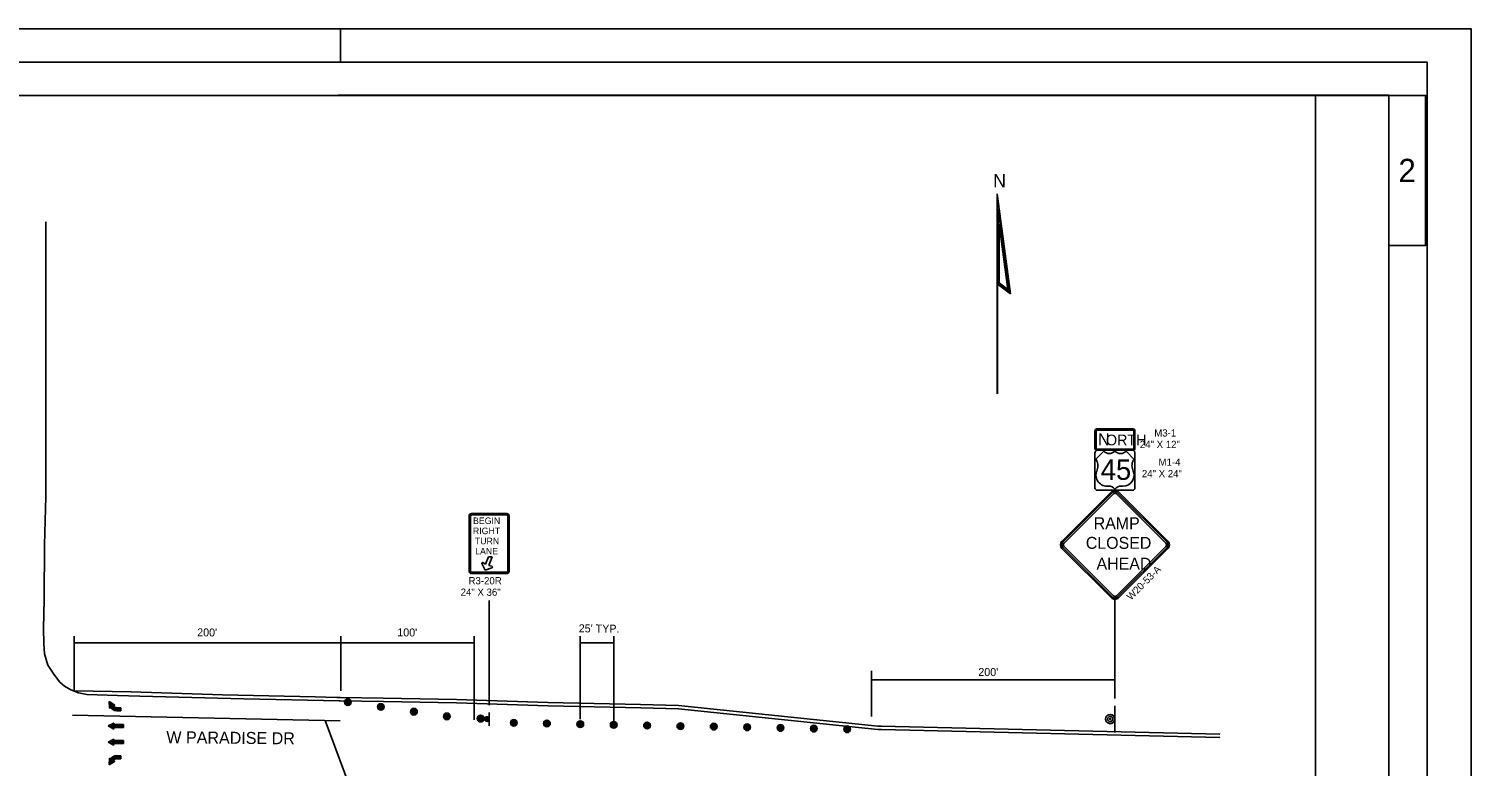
# Model space of a CAD drawing. Extents: x 360065 to 362124, y 174333 to 175433.
# Drawn here: x 361043 to 362124, y 174880 to 175433 of the extents above; entities that cross this region are included whole.
import ezdxf

# ---------------------------------------------------------------- set-up
doc = ezdxf.new("R2010")
doc.units = 0
for name, color, linetype in [('Default', 7, 'Continuous'), ('P_ALI_100_Equation', 7, 'Continuous'), ('P_ALI_100_PIData', 7, 'Continuous'), ('P_ALI_100_Sta', 7, 'Continuous'), ('P_ALI_20', 7, 'Continuous'), ('P_ALI_200_Equation', 7, 'Continuous'), ('P_ALI_20_Equation', 7, 'Continuous'), ('P_ALI_20_Sta', 7, 'Continuous'), ('P_ALI_500_Equation', 7, 'Continuous'), ('P_ALI_500_PIData', 7, 'Continuous'), ('P_ALI_500_Sta', 7, 'Continuous'), ('P_ALI_50_Equation', 7, 'Continuous'), ('P_ALI_50_Tic', 7, 'Continuous')]:
    doc.layers.add(name, color=color, linetype=linetype)

msp = doc.modelspace()

# ---------------------------------------------------------------- linework, layer by layer
for p, q in [((361251.6, 175433), (361301.6, 175433)), ((361276.6, 175433), (361276.6, 175408)), ((362074.1, 175433), (362124.1, 175433)), ((362124.1, 175383), (362124.1, 175433)), ((360487.4, 175383), (362062.4, 175383)), ((362062.4, 174383), (362062.4, 175383))]:
    msp.add_line(p, q)
msp.add_lwpolyline([(362062.4, 175383), (362089.9, 175383), (362089.9, 175270.5), (362062.4, 175270.5)], close=True)
at = {"layer": 'Default'}
msp.add_lwpolyline([(362007.4, 175383), (362007.4, 174984.3), (362007.4, 174408.5), (360514, 174408), (360560.9, 175383)], close=True, dxfattribs=at)
msp.add_lwpolyline([(362007.4, 175383), (362007.4, 174984.3), (362007.4, 174408.5), (360514, 174408), (360560.9, 175383)], close=True, dxfattribs=at)
msp.add_lwpolyline([(362007.4, 175383), (362007.4, 174984.3), (362007.4, 174408.5), (360514, 174408), (360560.9, 175383)], close=True, dxfattribs=at)
at = {"layer": 'P_ALI_100_Equation'}
for p, q in [((361778.8, 175234.2), (361768.8, 175309.2)), ((361768.8, 175241.7), (361768.8, 175309.2)), ((361769.6, 175242), (361769.6, 175297.9)), ((361777.9, 175235.8), (361769.6, 175297.9)), ((361770.3, 175242.4), (361770.3, 175286.6)), ((361776.9, 175237.5), (361770.3, 175286.6)), ((361768.8, 175241.7), (361778.8, 175234.2)), ((361768.8, 175159.2), (361768.8, 175241.7)), ((361769.1, 175159.2), (361769.1, 175241.5)), ((361769.6, 175242), (361777.9, 175235.8)), ((361770.3, 175242.4), (361776.9, 175237.5))]:
    msp.add_line(p, q, dxfattribs=at)
msp.add_lwpolyline([(361768.9, 175309.1), (361768.8, 175309.1)], dxfattribs=at)
at = {"layer": 'P_ALI_100_PIData'}
for p, q in [((361388, 174925.8), (361388, 175004.3)), ((361857.1, 174931), (361857.1, 175005.2)), ((361076.9, 174936.6), (361076.9, 174977.6)), ((361076.9, 174972.6), (361276.9, 174972.6)), ((361276.9, 174936.6), (361276.9, 174977.6)), ((361276.9, 174972.6), (361376.9, 174972.6)), ((361376.9, 174915), (361376.9, 174977.6)), ((361456.4, 174915.5), (361456.4, 174977.6)), ((361456.4, 174972.6), (361481.4, 174972.6)), ((361481.4, 174914), (361481.4, 174977.6)), ((361674.6, 174917.4), (361674.6, 174951.6)), ((361674.6, 174944.9), (361857.1, 174944.9)), ((361265.1, 174914.4), (361305.2, 174806.8))]:
    msp.add_line(p, q, dxfattribs=at)
at = {"layer": 'P_ALI_100_Sta'}
for p, q in [((361304.6, 174929.6), (361304.6, 174929.6)), ((361329.4, 174926.1), (361329.4, 174926.1)), ((361354.1, 174922.5), (361354.1, 174922.5)), ((361378.9, 174919), (361378.9, 174919)), ((361388, 174920.5), (361388, 174910.5)), ((361857.1, 174925.5), (361857.1, 174905.5)), ((361404.2, 174915.3), (361404.2, 174915.3)), ((361428.9, 174912.2), (361428.9, 174912.2)), ((361453.9, 174911.8), (361453.9, 174911.8)), ((361478.9, 174911.3), (361478.9, 174911.3)), ((361503.9, 174910.8), (361503.9, 174910.8)), ((361528.9, 174910.3), (361528.9, 174910.3)), ((361553.9, 174909.8), (361553.9, 174909.8)), ((361578.9, 174909.3), (361578.9, 174909.3)), ((361603.9, 174908.8), (361603.9, 174908.8)), ((361628.9, 174908.3), (361628.9, 174908.3)), ((361653.9, 174907.8), (361653.9, 174907.8)), ((361678.9, 174907.4), (361678.9, 174907.4))]:
    msp.add_line(p, q, dxfattribs=at)
for centre, radius in [((361282.2, 174928.1), 2.5), ((361282.2, 174928.1), 2), ((361282.2, 174928.1), 1.5), ((361282.2, 174928.1), 1), ((361282.2, 174928.1), 0.5), ((361282.2, 174928.1), 0.25), ((361306.9, 174924.6), 2.5), ((361306.9, 174924.6), 2), ((361306.9, 174924.6), 1.5), ((361306.9, 174924.6), 1), ((361306.9, 174924.6), 0.5), ((361306.9, 174924.6), 0.25), ((361331.7, 174921), 2.5), ((361331.7, 174921), 2), ((361331.7, 174921), 1.5), ((361331.7, 174921), 1), ((361331.7, 174921), 0.5), ((361331.7, 174921), 0.25), ((361356.4, 174917.5), 2.5), ((361356.4, 174917.5), 2), ((361356.4, 174917.5), 1.5), ((361356.4, 174917.5), 1), ((361356.4, 174917.5), 0.5), ((361356.4, 174917.5), 0.25), ((361381.7, 174915.8), 2.5), ((361381.7, 174915.8), 2), ((361381.7, 174915.8), 1.5), ((361381.7, 174915.8), 1), ((361381.7, 174915.8), 0.5), ((361381.7, 174915.8), 0.25), ((361386.3, 174915.5), 1.75), ((361386.3, 174915.5), 1), ((361386.3, 174915.5), 0.25), ((361853.6, 174915.5), 3.5), ((361853.6, 174915.5), 2), ((361853.6, 174915.5), 0.5), ((361406.5, 174912.7), 2.5), ((361406.5, 174912.7), 2), ((361406.5, 174912.7), 1.5), ((361406.5, 174912.7), 1), ((361406.5, 174912.7), 0.5), ((361406.5, 174912.7), 0.25), ((361431.4, 174912.2), 2.5), ((361431.4, 174912.2), 2), ((361431.4, 174912.2), 1.5), ((361431.4, 174912.2), 1), ((361431.4, 174912.2), 0.5), ((361431.4, 174912.2), 0.25), ((361456.4, 174911.7), 2.5), ((361456.4, 174911.7), 2), ((361456.4, 174911.7), 1.5), ((361456.4, 174911.7), 1), ((361456.4, 174911.7), 0.5), ((361456.4, 174911.7), 0.25), ((361481.4, 174911.2), 2.5), ((361481.4, 174911.2), 2), ((361481.4, 174911.2), 1.5), ((361481.4, 174911.2), 1), ((361481.4, 174911.2), 0.5), ((361481.4, 174911.2), 0.25), ((361506.4, 174910.7), 2.5), ((361506.4, 174910.7), 2), ((361506.4, 174910.7), 1.5), ((361506.4, 174910.7), 1), ((361506.4, 174910.7), 0.5), ((361506.4, 174910.7), 0.25), ((361531.4, 174910.2), 2.5), ((361531.4, 174910.2), 2), ((361531.4, 174910.2), 1.5), ((361531.4, 174910.2), 1), ((361531.4, 174910.2), 0.5), ((361531.4, 174910.2), 0.25), ((361556.4, 174909.8), 2.5), ((361556.4, 174909.8), 2), ((361556.4, 174909.8), 1.5), ((361556.4, 174909.8), 1), ((361556.4, 174909.8), 0.5), ((361556.4, 174909.8), 0.25), ((361581.4, 174909.3), 2.5), ((361581.4, 174909.3), 2), ((361581.4, 174909.3), 1.5), ((361581.4, 174909.3), 1), ((361581.4, 174909.3), 0.5), ((361581.4, 174909.3), 0.25), ((361606.4, 174908.8), 2.5), ((361606.4, 174908.8), 2), ((361606.4, 174908.8), 1.5), ((361606.4, 174908.8), 1), ((361606.4, 174908.8), 0.5), ((361606.4, 174908.8), 0.25), ((361631.4, 174908.3), 2.5), ((361631.4, 174908.3), 2), ((361631.4, 174908.3), 1.5), ((361631.4, 174908.3), 1), ((361631.4, 174908.3), 0.5), ((361631.4, 174908.3), 0.25), ((361656.4, 174907.8), 2.5), ((361656.4, 174907.8), 2), ((361656.4, 174907.8), 1.5), ((361656.4, 174907.8), 1), ((361656.4, 174907.8), 0.5), ((361656.4, 174907.8), 0.25)]:
    msp.add_circle(centre, radius, dxfattribs=at)
at = {"layer": 'P_ALI_20'}
for points in [[(360424.1, 174333), (362124.1, 174333), (362124.1, 175433), (360424.1, 175433)], [(360436.1, 174358), (362091.1, 174358), (362091.1, 175408), (360436.1, 175408)]]:
    msp.add_lwpolyline(points, close=True, dxfattribs=at)
at = {"layer": 'P_ALI_200_Equation'}
msp.add_lwpolyline([(360424.1, 175433), (362124.1, 175433), (362124.1, 174333), (360424.1, 174333), (360424.1, 175433)], dxfattribs=at)
at = {"layer": 'P_ALI_20_Equation'}
msp.add_line((361055.7, 175082.2), (361055.7, 175288.2), dxfattribs=at)
for points in [[(361275.8, 174929.2), (361204.1, 174930.7), (361126.3, 174932.7), (361109.6, 174933.2), (361086.5, 174934), (361080.3, 174935.2), (361074.6, 174937.5), (361069.8, 174940.2), (361066.4, 174943.2), (361062.4, 174948.3), (361057.3, 174955.8), (361054.8, 174964.4), (361054.2, 174972.2), (361054, 174983), (361054.6, 175005.3), (361054.9, 175046.1), (361055.7, 175082.2)], [(361273.8, 174931.7), (361257.6, 174932.2), (361188.2, 174933.7), (361119.7, 174935.9), (361076.9, 174936.6), (361076.9, 174936.6), (361076.9, 174936.6)], [(361530.1, 174925.7), (361501.6, 174926.5), (361432.1, 174928), (361363.7, 174930.2), (361308.7, 174931.1), (361276.4, 174931.6), (361273.8, 174931.7)], [(361530.1, 174923.2), (361501.7, 174924), (361432.2, 174925.5), (361363.7, 174927.7), (361308.8, 174928.6), (361276.4, 174929.1), (361275.7, 174929.2)], [(361679.4, 174910.2), (361530.1, 174925.7)], [(361679.4, 174907.7), (361530.1, 174923.2)], [(361935.8, 174904.2), (361935.8, 174904.2), (361935.8, 174904.2), (361935.8, 174904.2), (361935.8, 174904.2), (361682, 174910.2), (361679.4, 174910.2)], [(361935.7, 174901.7), (361935.7, 174901.7), (361935.7, 174901.7), (361935.7, 174901.7), (361935.7, 174901.7), (361682.1, 174907.7), (361679.4, 174907.7)]]:
    msp.add_lwpolyline(points, dxfattribs=at)
at = {"layer": 'P_ALI_20_Sta'}
msp.add_lwpolyline([(360424.1, 175433), (362124.1, 175433), (362124.1, 174333), (360424.1, 174333)], close=True, dxfattribs=at)
at = {"layer": 'P_ALI_500_Equation'}
msp.add_line((361276.4, 174914.2), (361075.8, 174918.3), dxfattribs=at)
at = {"layer": 'P_ALI_500_PIData'}
for p, q in [((361107.5, 174925.9), (361103.3, 174928.6)), ((361103.3, 174928.6), (361103.6, 174923.6)), ((361105.3, 174924.6), (361103.4, 174928.1)), ((361104.9, 174924.4), (361103.4, 174927.1)), ((361105.7, 174924.9), (361103.7, 174928.3)), ((361106.1, 174925.1), (361104.6, 174927.8)), ((361106.5, 174925.3), (361105.4, 174927.2)), ((361106.9, 174925.5), (361106.2, 174926.7)), ((361104.6, 174924.2), (361103.5, 174926.1)), ((361104.2, 174924), (361103.5, 174925.1)), ((361103.6, 174923.6), (361104.6, 174924.2)), ((361103.8, 174923.7), (361103.6, 174924.1)), ((361106.5, 174925.3), (361107.5, 174925.9)), ((361107.3, 174925.8), (361107.1, 174926.2)), ((361112, 174923.9), (361108.9, 174923.9)), ((361112, 174923.5), (361108.9, 174923.5)), ((361112, 174923), (361108.9, 174923)), ((361112, 174922.6), (361108.9, 174922.6)), ((361112, 174922.1), (361108.9, 174922.1)), ((361112, 174921.7), (361108.9, 174921.7)), ((361112, 174921.7), (361112, 174923.9)), ((361112, 174922.8), (361112, 174922.8)), ((361102.4, 174910.3), (361106.8, 174912.5)), ((361102.4, 174910.3), (361106.8, 174908)), ((361113.9, 174910.5), (361102.8, 174910.5)), ((361113.9, 174910), (361102.9, 174910)), ((361113.9, 174910.9), (361103.7, 174910.9)), ((361113.9, 174909.6), (361103.8, 174909.6)), ((361106.8, 174911.4), (361104.6, 174911.4)), ((361106.8, 174909.1), (361104.7, 174909.1)), ((361106.8, 174911.8), (361105.5, 174911.8)), ((361106.8, 174908.7), (361105.5, 174908.7)), ((361106.8, 174912.3), (361106.4, 174912.3)), ((361106.8, 174908.2), (361106.4, 174908.2)), ((361106.8, 174912.5), (361106.8, 174908)), ((361113.9, 174911.4), (361106.8, 174911.4)), ((361113.9, 174909.1), (361106.8, 174909.1)), ((361113.9, 174911.4), (361113.9, 174909.1)), ((361113.9, 174910.3), (361113.9, 174910.3)), ((361102.4, 174898.2), (361106.8, 174900.5)), ((361102.4, 174898.2), (361106.8, 174896)), ((361113.9, 174898.4), (361102.8, 174898.4)), ((361113.9, 174898), (361102.9, 174898)), ((361113.9, 174898.9), (361103.7, 174898.9)), ((361113.9, 174897.5), (361103.8, 174897.5)), ((361106.8, 174899.3), (361104.6, 174899.3)), ((361106.8, 174897.1), (361104.7, 174897.1)), ((361106.8, 174899.8), (361105.5, 174899.8)), ((361106.8, 174896.6), (361105.5, 174896.6)), ((361106.8, 174900.2), (361106.4, 174900.2)), ((361106.8, 174896.2), (361106.4, 174896.2)), ((361106.8, 174900.5), (361106.8, 174896)), ((361113.9, 174899.3), (361106.8, 174899.3)), ((361113.9, 174897.1), (361106.8, 174897.1)), ((361113.9, 174899.3), (361113.9, 174897.1)), ((361113.9, 174898.2), (361113.9, 174898.2)), ((361103.3, 174881.1), (361103.6, 174886.1)), ((361107.5, 174883.8), (361103.3, 174881.1)), ((361104.9, 174885.3), (361103.4, 174882.6)), ((361105.3, 174885), (361103.4, 174881.6)), ((361104.2, 174885.7), (361103.5, 174884.6)), ((361104.6, 174885.5), (361103.5, 174883.6)), ((361103.6, 174886.1), (361104.6, 174885.5)), ((361103.8, 174885.9), (361103.6, 174885.6)), ((361105.7, 174884.8), (361103.7, 174881.4)), ((361106.1, 174884.6), (361104.6, 174881.9)), ((361106.5, 174884.4), (361105.4, 174882.5)), ((361106.9, 174884.1), (361106.2, 174883)), ((361106.5, 174884.4), (361107.5, 174883.8)), ((361107.3, 174883.9), (361107.1, 174883.5)), ((361112, 174888), (361108.9, 174888)), ((361112, 174887.5), (361108.9, 174887.5)), ((361112, 174887.1), (361108.9, 174887.1)), ((361112, 174886.6), (361108.9, 174886.6)), ((361112, 174886.2), (361108.9, 174886.2)), ((361112, 174885.7), (361108.9, 174885.7)), ((361112, 174888), (361112, 174885.7)), ((361112, 174886.9), (361112, 174886.9))]:
    msp.add_line(p, q, dxfattribs=at)
for centre, radius, start, end in [((361108.9, 174926.7), 5.03, 209.9967, 270), ((361108.9, 174926.7), 4.58, 209.9967, 270), ((361108.9, 174926.7), 4.13, 209.9967, 270), ((361108.9, 174926.7), 3.68, 209.9967, 270), ((361108.9, 174926.7), 3.23, 209.9967, 270), ((361108.9, 174926.7), 2.78, 209.9967, 270), ((361108.9, 174883), 5.03, 90, 150.0033), ((361108.9, 174883), 4.58, 90, 150.0033), ((361108.9, 174883), 4.13, 90, 150.0033), ((361108.9, 174883), 3.68, 90, 150.0033), ((361108.9, 174883), 3.23, 90, 150.0033), ((361108.9, 174883), 2.78, 90, 150.0033)]:
    msp.add_arc(centre, radius, start, end, dxfattribs=at)
at = {"layer": 'P_ALI_500_Sta'}
for p, q in [((361843.6, 175133), (361870.6, 175133)), ((361843.6, 175132.6), (361870.6, 175132.6)), ((361843.6, 175132.1), (361870.6, 175132.1)), ((361842.1, 175131.5), (361842.1, 175118.5)), ((361842.5, 175131.5), (361842.5, 175118.5)), ((361843, 175131.5), (361843, 175118.5)), ((361871.2, 175131.5), (361871.2, 175118.5)), ((361871.7, 175131.5), (361871.7, 175118.5)), ((361872.1, 175131.5), (361872.1, 175118.5)), ((361842.1, 175088.8), (361842.1, 175115.1)), ((361848.8, 175116.3), (361842.8, 175110.3)), ((361870.6, 175117.8), (361843.6, 175117.8)), ((361870.6, 175117.3), (361843.6, 175117.3)), ((361870.6, 175117), (361843.6, 175117)), ((361844, 175117), (361870.2, 175117)), ((361871.4, 175110.3), (361865.5, 175116.3)), ((361872.1, 175115.1), (361872.1, 175088.8)), ((361851.2, 175090.1), (361852.4, 175090.1)), ((361861.9, 175090.1), (361863.1, 175090.1)), ((361857.1, 175087), (361844, 175087)), ((361870.2, 175087), (361857.1, 175087)), ((361870.2, 175087), (361870.2, 175087)), ((361385.4, 175031.5), (361387.7, 175037.1)), ((361390.4, 175037.1), (361387.7, 175037.1)), ((361387.8, 175030.6), (361390.4, 175037.1)), ((361382.6, 175032), (361385, 175027.1)), ((361383.5, 175032.7), (361385.4, 175031.5)), ((361390.1, 175028.9), (361385, 175027.1)), ((361390, 175030.1), (361387.8, 175030.6))]:
    msp.add_line(p, q, dxfattribs=at)
for points in [[(361854.5, 175085.9), (361817.3, 175048.7)], [(361855.1, 175085.2), (361818, 175048.1)], [(361856, 175084.4), (361818.9, 175047.2)], [(361895.4, 175047.2), (361858.3, 175084.4)], [(361896.2, 175048.1), (361859.1, 175085.2)], [(361896.9, 175048.7), (361859.8, 175085.9)], [(361373, 175067.7), (361373, 175026.4)], [(361373.5, 175067.7), (361373.5, 175026.4)], [(361374.1, 175067.7), (361374.1, 175026.4)], [(361401.2, 175069.6), (361374.9, 175069.6)], [(361401.2, 175069.1), (361374.9, 175069.1)], [(361401.2, 175068.5), (361374.9, 175068.5)], [(361402, 175026.4), (361402, 175067.7)], [(361402.6, 175026.4), (361402.6, 175067.7)], [(361403, 175026.4), (361403, 175067.7)], [(361817.3, 175043.4), (361854.5, 175006.3)], [(361818, 175044.1), (361855.1, 175007)], [(361818.9, 175045), (361856, 175007.8)], [(361858.3, 175007.9), (361895.4, 175045)], [(361859.1, 175007), (361896.2, 175044.1)], [(361859.8, 175006.4), (361896.9, 175043.5)], [(361374.9, 175025.7), (361401.2, 175025.7)], [(361374.9, 175025), (361401.2, 175025)], [(361374.9, 175024.6), (361401.2, 175024.6)]]:
    msp.add_lwpolyline(points, dxfattribs=at)
for centre, radius, start, end in [((361843.6, 175131.5), 1.5, 90.7657, 180), ((361843.6, 175131.5), 1.12, 90, 180), ((361843.6, 175131.5), 0.625, 90, 180), ((361870.6, 175131.5), 1.5, 0, 90), ((361870.6, 175131.5), 1.12, 0, 90), ((361870.6, 175131.5), 0.625, 0, 90), ((361843.6, 175118.5), 1.5, 180, 270), ((361844, 175115.1), 1.87, 90, 180), ((361843.6, 175118.5), 1.12, 180, 270), ((361836.1, 175105.4), 8.33, 338.8697, 35.952), ((361843.6, 175118.5), 0.625, 180, 270), ((361852.9, 175120.5), 5.95, 225.5728, 314.4272), ((361861.3, 175120.5), 5.95, 225.5728, 314.4272), ((361878.2, 175105.5), 8.33, 144.2681, 203.1411), ((361870.2, 175115.1), 1.87, 0, 90), ((361870.6, 175118.5), 1.12, 270, 360), ((361870.6, 175118.5), 0.625, 270, 360), ((361870.6, 175118.5), 1.5, 270, 360), ((361851.2, 175098.4), 8.33, 151.2519, 270.0001), ((361863.1, 175098.4), 8.33, 269.9999, 26.8465), ((361844, 175088.8), 1.87, 180, 270), ((361852.3, 175084.1), 6.03, 37.2122, 89.6577), ((361861.9, 175084.1), 6.03, 90.3423, 142.7878), ((361870.2, 175088.8), 1.87, 270, 360), ((361857.1, 175083.2), 3.75, 44.9981, 135), ((361857.1, 175083.2), 2.8, 44.9981, 135), ((361857.1, 175083.2), 1.61, 44.9981, 135), ((361374.9, 175067.7), 1.88, 90, 180), ((361374.9, 175067.7), 1.41, 90, 180), ((361374.9, 175067.7), 0.781, 90, 180), ((361401.2, 175067.7), 1.88, 0, 90), ((361401.2, 175067.7), 1.41, 0, 90), ((361401.2, 175067.7), 0.781, 0, 90), ((361820, 175046.1), 3.75, 135, 225), ((361820, 175046.1), 2.8, 135, 225), ((361820, 175046.1), 1.61, 135, 225), ((361894.2, 175046.1), 1.61, 315, 45), ((361894.2, 175046.1), 2.8, 315, 45), ((361894.2, 175046.1), 3.75, 315, 45), ((361374.9, 175026.4), 1.88, 180, 270), ((361374.9, 175026.4), 1.41, 180, 270), ((361374.9, 175026.4), 0.781, 180, 270), ((361383.2, 175032.2), 0.625, 57.4706, 200.3737), ((361389.9, 175029.5), 0.625, 292.3864, 78.7997), ((361401.2, 175026.4), 1.41, 270, 0), ((361401.2, 175026.4), 1.88, 270, 0), ((361401.2, 175026.4), 0.781, 270, 0), ((361857.1, 175009), 3.75, 225.0072, 315.6509), ((361857.1, 175009), 2.8, 225.0072, 315.6509), ((361857.1, 175009), 1.61, 225.0072, 315.6509)]:
    msp.add_arc(centre, radius, start, end, dxfattribs=at)
at = {"layer": 'P_ALI_50_Tic'}
msp.add_lwpolyline([(362062, 175383.5), (360487.4, 175383), (360487.7, 174408)], dxfattribs=at)

# ---------------------------------------------------------------- texts
msp.add_text('2', height=17.5, rotation=360).set_placement((362069.6, 175318))
at = {"layer": 'P_ALI_100_Equation'}
msp.add_text('N', height=10, dxfattribs=at).set_placement((361765.8, 175314.1))
at = {"layer": 'P_ALI_500_Sta'}
for s, height, p in [('M3-1', 5.4, (361886.6, 175127.3)), ('N', 9.14, (361844.4, 175120.6)), ('ORTH', 8, (361850.4, 175120.7)), ('24" X 12"', 5.4, (361875.8, 175118.7)), ('45', 15.33, (361846.5, 175094.8)), ('M1-4', 5.4, (361889.8, 175105.4)), ('24" X 24"', 5.4, (361877.3, 175096.8)), ('RIGHT', 4.9, (361375.9, 175054.1)), ('BEGIN', 4.9, (361376, 175061.7)), ('RAMP', 8.93, (361841.2, 175057.8)), ('TURN', 4.9, (361377.4, 175046.5)), ('CLOSED', 8.93, (361835.3, 175043.1)), ('LANE', 4.9, (361377.6, 175038.9)), ('AHEAD', 8.93, (361843.3, 175027.5)), ('24" X 36"', 5.4, (361366.7, 175007.9)), ('R3-20R', 5.4, (361372.6, 175016.5))]:
    msp.add_text(s, height=height, dxfattribs=at).set_placement(p)
msp.add_text('W20-53-A', height=5.4, rotation=45, dxfattribs=at).set_placement((361869.1, 175004.2))
at = {"layer": 'P_ALI_50_Equation'}
for s, height, p in [("200'", 6, (361169.2, 174977.5)), ("100'", 6, (361319.2, 174977.5)), ("25' TYP.", 6, (361455.2, 174980.5)), ("200'", 6, (361754.7, 174947.8)), ('W PARADISE DR', 9, (361146.1, 174897.4))]:
    msp.add_text(s, height=height, rotation=359.4382, dxfattribs=at).set_placement(p)

doc.saveas('drawing.dxf')
